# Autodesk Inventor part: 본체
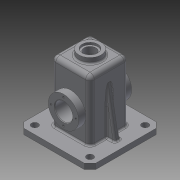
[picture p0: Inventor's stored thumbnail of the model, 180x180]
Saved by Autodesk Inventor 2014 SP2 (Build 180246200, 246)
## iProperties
Created: 2016-02
Part Number: 본체
Material: 일반
Document SubType Name: Modeling
Designer: 1sil_ho3333
Density: 1 g/cm^3
Appearance: 기본값
Author: 1sil_ho3333
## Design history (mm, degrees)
sketch "스케치1"
  geometry: L1 (65, -65)-(-65, -65); L2 (-65, -65)-(-65, 65); L3 (-65, 65)-(65, 65); L4 (65, 65)-(65, -65); 1 further point
  constraints: 8 end point, 2 parallel, 1 horizontal, 1 perpendicular
  dimensions: "d0" = 130 distance of L2.end L3.end; "d1" = 130 distance of L3.end L1.start; "d2" = 65 distance from line of point (0, 0) L1; "d3" = 65 distance from line of point (0, 0) L2
extrude "돌출1" new body sketch "스케치1" distance "d4" = 10; taper "d5" = 0 deg
chamfer "모따기1" distance "d6" = 10; stored, may be unused: second distance "d7" = 2, angle "d8" = 45 deg
sketch "스케치2"
  geometry: L1 (35, -35)-(-35, -35); L2 (-35, -35)-(-35, 35); L3 (-35, 35)-(35, 35); L4 (35, 35)-(35, -35); 1 further point
  constraints: 8 end point, 2 parallel, 1 horizontal, 1 perpendicular
  dimensions: "d9" = 70 distance of L2.end L3.end; "d10" = 70 distance of L3.end L1.start; "d11" = 35 distance from line of point (0, 0) L1; "d12" = 35 distance from line of point (0, 0) L2
extrude "돌출2" join sketch "스케치2" distance "d13" = 110; taper "d14" = 0 deg
node "작업 평면1"
sketch "스케치3"
  geometry: C1 r 20 at (0, 0); 1 further point
  constraints: 1 centre point, 1 coincident
  dimensions: "d16" = 40 diameter of C1
extrude "돌출3" join sketch "스케치3" distance "d17" = 30; taper "d18" = 0 deg
node "작업 평면2"
sketch "스케치4"
  geometry: L1 (0, 0)-(0, 55); C1 r 27.5 at (0, 55)
  constraints: 2 end point, 1 centre point, 1 coincident, 1 vertical
  dimensions: "d20" = 55 distance of L1.start L1.end; "d21" = 55 diameter of C1
extrude "돌출4" join sketch "스케치4" distance "d22" = 30; taper "d23" = 0 deg
sketch "스케치6"
  geometry: L1 (30, 115)-(-30, 115); L2 (35, 10)-(35, 120) reference; L3 (-35, 10)-(-35, 120) reference; L4 (35, 120)-(-35, 120) reference; L5 (-55, 0)-(55, 0) reference; L6 (-55, 55)-(55, 55); L7 (-55, 82.5)-(55, 82.5); L8 (-55, 27.5)-(55, 27.5); L9 (-30, 82.5)-(-23, 75.5); L10 (-30, 27.5)-(-23, 34.5); L11 (-23, 34.5)-(-23, 75.5); L12 (-30, 0)-(-30, 27.5); L13 (-30, 82.5)-(-30, 115); L14 (0, 0)-(0, 115); L15 (30, 82.5)-(30, 115); L16 (30, 82.5)-(23, 75.5); L17 (23, 34.5)-(23, 75.5); L18 (30, 27.5)-(23, 34.5); L19 (30, 0)-(30, 27.5); L20 (30, 0)-(30, 27.5); L21 (30, 82.5)-(30, 115)
  constraints: 34 end point, 8 parallel, 6 point on line, 4 symmetric about line, 1 midpoint, 1 perpendicular
  dimensions: "d25" = 5 distance between parallel lines of L4 L1; "d27" = 55 distance between parallel lines of L5 L6; "d28" = 27.5 distance between parallel lines of L6 L7; "d29" = 55 distance between parallel lines of L8 L7; "d32" = 55 distance of L10.start L9.start; "d33" = 55 distance of L18.start L15.start (derived); "d34" = 58 distance between parallel lines of L2 L11; "d35" = 65 distance between parallel lines of L2 L13; "d36" = 20 distance from line of L7.end L2; "d37" = 20 distance from line of L6.end L2; "d38" = 20 distance from line of L8.end L2; "d39" = 90 distance from line of L7.start L2; "d40" = 90 distance from line of L6.start L2; "d41" = 90 distance from line of L8.start L2
extrude "돌출5" cut sketch "스케치6" stored distance "d42" = 60; taper "d43" = 0 deg
sketch "스케치7"
  geometry: C1 r 27.5 at (0, 0) reference; C2 r 16 at (0, 0); 1 further point
  constraints: 1 centre point, 1 coincident
  dimensions: "d44" = 32 diameter of C2
extrude "돌출6" cut sketch "스케치7" distance "d45" = 50; taper "d46" = 0 deg
sketch "스케치8"
  geometry: L1 (0, 0)-(0, 22.5); C1 r 27.5 at (0, 0) reference; 2 further points
  constraints: 2 end point, 1 coincident, 1 vertical
  dimensions: "d47" = 22.5 distance of L1.start L1.end
hole "구멍1" sketch "스케치8" at (0, 22.5) diameter "d48" = 3.459; stored, may be unused: countersink angle "d52" = 90 deg, drill point angle "d54" = 118 deg; dims "d49" = 8, "d50" = 4, "d51" = 2, "d53" = 10
node "작업 평면3"
sketch "스케치11"
  geometry: L1 (0, 0)-(0, 55); C1 r 27.5 at (0, 55)
  constraints: 2 end point, 1 centre point, 1 coincident, 1 vertical
  dimensions: "d59" = 55 distance of L1.start L1.end; "d60" = 55 diameter of C1
extrude "돌출7" join sketch "스케치11" distance "d61" = 15; taper "d62" = 0 deg
sketch "스케치14"
  geometry: C1 r 20 at (0, 0) reference; C2 r 14 at (0, 0)
  constraints: 1 centre point, 1 coincident
  dimensions: "d63" = 28 diameter of C2
extrude "돌출8" cut sketch "스케치14" distance "d64" = 4; taper "d65" = 0 deg
sketch "스케치15"
  geometry: C1 r 14 at (0, 0) reference; C2 r 10.5 at (0, 0)
  constraints: 1 centre point, 1 coincident
  dimensions: "d66" = 21 diameter of C2
extrude "돌출9" cut sketch "스케치15" distance "d67" = 50; taper "d68" = 0 deg
sketch "스케치16"
  geometry: L1 (65, 10)-(65, 0) reference; L2 (50, 10)-(50, 0); L3 (35, 10)-(35, 120) reference; L4 (50, 10)-(35, 95.069); L5 (50, 10)-(35, 10); L6 (35, 10)-(35, 95.069); 1 further point
  constraints: 8 end point, 2 perpendicular, 1 parallel, 1 point on line
  dimensions: "d69" = 15 distance between parallel lines of L1 L2; "d70" = 10 deg angle of L1 L4
extrude "돌출10" join sketch "스케치16" stored distance "d71" = 10; taper "d72" = 0 deg
fillet "모깎기1" dims "d73" = 8
fillet "모깎기2" dims "d74" = 8
fillet "모깎기3" dims "d75" = 3
fillet "모깎기4" dims "d76" = 3
sketch "스케치17"
  geometry: L1 (-55, -65)-(55, -65) reference; L2 (65, -55)-(65, 55) reference; L3 (-50, -50)-(50, -50); L4 (50, -50)-(50, 50); L5 (50, 50)-(-50, 50); L6 (-50, 50)-(-50, -50); C1 r 6 at (50, 50); C2 r 6 at (50, -50); C3 r 6 at (-50, -50); C4 r 6 at (-50, 50); 1 further point
  constraints: 8 end point, 4 centre point, 4 coincident, 3 equal radius, 2 parallel, 1 horizontal, 1 perpendicular
  dimensions: "d77" = 100 distance of L3.end L4.end; "d78" = 100 distance of L4.end L5.end; "d79" = 15 distance between parallel lines of L2 L4; "d80" = 15 distance between parallel lines of L1 L3; "d81" = 12 diameter of C1
extrude "돌출11" cut sketch "스케치17" distance "d82" = 15; taper "d83" = 0 deg
chamfer "모따기2" distance "d84" = 1; stored, may be unused: second distance "d85" = 2, angle "d86" = 45 deg
fillet "모깎기7" dims "d89" = 3
node "작업 평면4"
sketch "스케치18"
  geometry: L1 (-20, 130)-(20, 130) reference; L2 (35, 13)-(35, 112) reference; 2 further points
  constraints: 1 vertical alignment, 1 other
  dimensions: "d91" = 30 distance from line of L1 point (0, 100); "d92" = 35 distance from line of L2 point (0, 100) (derived)
feature "엠보싱1" sketch "스케치18" dims "d0" = 130, "d1" = 130, "d2" = 65, "d3" = 65, "d93" = 0.5, "d94" = 0
fillet "모깎기8" dims "d95" = 3
fillet "모깎기9" dims "d96" = 0.5
node "솔리드1"
pattern_circular "원형 패턴1" dims angle "d56" = 360 deg
mirror "대칭2"
mirror "대칭3"
other parameters: "d19" = -48, "d24" = 5, "d26" = 5, "d30" = 7, "d31" = 135 deg, "d58" = 48, "d90" = 72
